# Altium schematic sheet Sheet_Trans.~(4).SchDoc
size A4
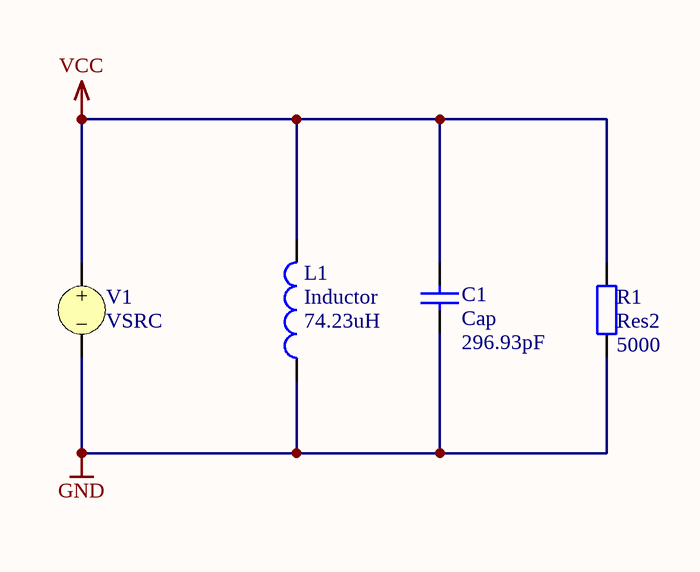
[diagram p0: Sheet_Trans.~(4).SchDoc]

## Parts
C1  Cap  value 296.93pF  [RAD-0.3]
L1  Inductor  value 74.23uH  [0402-A]
R1  Res2  value 5000  [AXIAL-0.4]
V1  VSRC

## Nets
GND: C1.1 L1.1 R1.1 V1.2
VCC: C1.2 L1.2 R1.2 V1.1

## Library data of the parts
C1 = Cap: Capacitor
L1 = Inductor: Code_IEC: 1005
R1 = Res2: Resistor
V1 = VSRC: Voltage Source; Note: PCB Footprint - Not required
